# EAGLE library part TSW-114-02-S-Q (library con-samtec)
THROUGH-HOLE .025" SQ POST HEADER Source: Samtec TSW.pdf
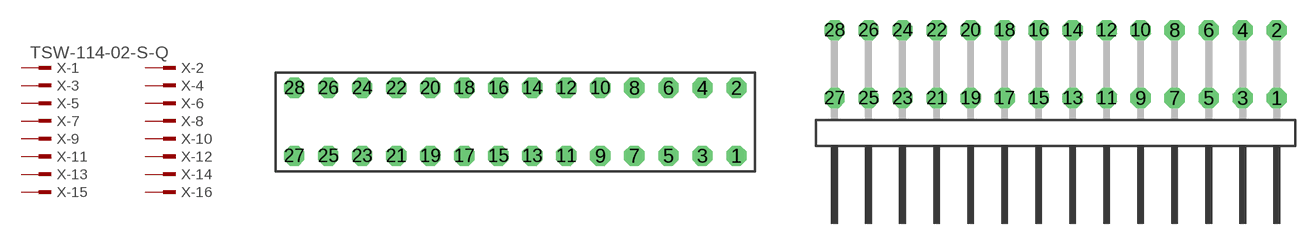
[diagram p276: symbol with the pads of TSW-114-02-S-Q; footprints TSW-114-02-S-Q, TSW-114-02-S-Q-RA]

Designator prefix X; gates -1=MPINV -2=MPIN -3=MPIN -4=MPIN -5=MPIN -6=MPIN -7=MPIN -8=MPIN -9=MPIN -10=MPIN -11=MPIN -12=MPIN -13=MPIN -14=MPIN -15=MPIN -16=MPIN -17=MPIN -18=MPIN -19=MPIN -20=MPIN -21=MPIN -22=MPIN -23=MPIN -24=MPIN -25=MPIN -26=MPIN -27=MPIN -28=MPIN

## TSW-114-02-S-Q (OC_FARNELL: unknown; OC_NEWARK: unknown)  [TSW-114-02-S-Q]
1  -1:1  pas
2  -2:1  pas
3  -3:1  pas
4  -4:1  pas
5  -5:1  pas
6  -6:1  pas
7  -7:1  pas
8  -8:1  pas
9  -9:1  pas
10  -10:1  pas
11  -11:1  pas
12  -12:1  pas
13  -13:1  pas
14  -14:1  pas
15  -15:1  pas
16  -16:1  pas
17  -17:1  pas
18  -18:1  pas
19  -19:1  pas
20  -20:1  pas
21  -21:1  pas
22  -22:1  pas
23  -23:1  pas
24  -24:1  pas
25  -25:1  pas
26  -26:1  pas
27  -27:1  pas
28  -28:1  pas

## TSW-114-02-S-Q-RA (OC_FARNELL: unknown; OC_NEWARK: unknown)  [TSW-114-02-S-Q-RA]
Pads as for TSW-114-02-S-Q

## Footprint TSW-114-02-S-Q (pad centres in mm)
THROUGH-HOLE .025" SQ POST HEADER Source: Samtec TSW.pdf
drill 1 pad 1.5 octagon: 1 16.51,-2.54; 2 16.51,2.54; 3 13.97,-2.54; 4 13.97,2.54; 5 11.43,-2.54; 6 11.43,2.54; 7 8.89,-2.54; 8 8.89,2.54; 9 6.35,-2.54; 10 6.35,2.54; 11 3.81,-2.54; 12 3.81,2.54; 13 1.27,-2.54; 14 1.27,2.54; 15 -1.27,-2.54; 16 -1.27,2.54; 17 -3.81,-2.54; 18 -3.81,2.54; 19 -6.35,-2.54; 20 -6.35,2.54; 21 -8.89,-2.54; 22 -8.89,2.54; 23 -11.43,-2.54; 24 -11.43,2.54; 25 -13.97,-2.54; 26 -13.97,2.54; 27 -16.51,-2.54; 28 -16.51,2.54

## Footprint TSW-114-02-S-Q-RA (pad centres in mm)
THROUGH-HOLE .025" SQ POST HEADER Source: Samtec TSW.pdf
drill 1 pad 1.5 octagon: 1 16.51,1.524; 2 16.51,6.604; 3 13.97,1.524; 4 13.97,6.604; 5 11.43,1.524; 6 11.43,6.604; 7 8.89,1.524; 8 8.89,6.604; 9 6.35,1.524; 10 6.35,6.604; 11 3.81,1.524; 12 3.81,6.604; 13 1.27,1.524; 14 1.27,6.604; 15 -1.27,1.524; 16 -1.27,6.604; 17 -3.81,1.524; 18 -3.81,6.604; 19 -6.35,1.524; 20 -6.35,6.604; 21 -8.89,1.524; 22 -8.89,6.604; 23 -11.43,1.524; 24 -11.43,6.604; 25 -13.97,1.524; 26 -13.97,6.604; 27 -16.51,1.524; 28 -16.51,6.604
